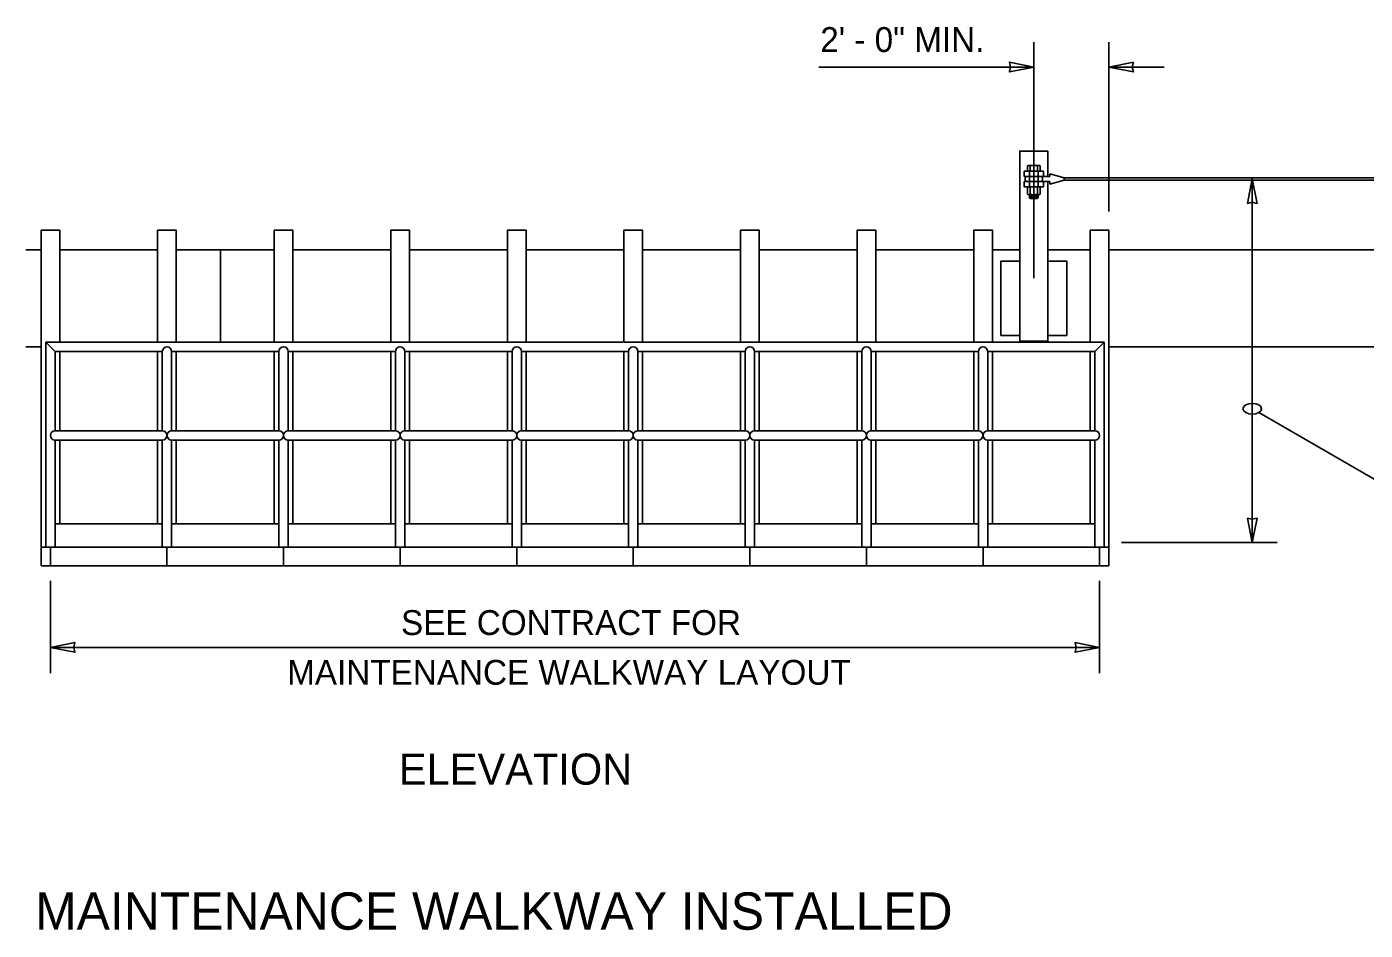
# Model space of a CAD drawing. Extents: x 99862 to 103151, y 100000 to 108076.
# Drawn here: x 100813 to 101674, y 101036 to 101617 of the extents above; entities that cross this region are included whole.
import ezdxf

# ---------------------------------------------------------------- set-up
doc = ezdxf.new("R2010")
doc.units = 0
for name, color, linetype in [('Level 15', 7, 'Continuous'), ('Level 18', 7, 'Continuous'), ('Level 2', 7, 'Continuous'), ('Level 20', 7, 'Continuous'), ('Level 22', 7, 'Continuous'), ('Level 23', 7, 'Continuous'), ('Level 27', 7, 'Continuous'), ('Level 4', 7, 'Continuous')]:
    doc.layers.add(name, color=color, linetype=linetype)

msp = doc.modelspace()

# ---------------------------------------------------------------- linework, layer by layer
at = {"layer": 'Level 15'}
for p, q in [((101460.79, 101607.01), (101460.79, 101455.11)), ((101509.12, 101498.01), (101509.12, 101607.01)), ((101322.46, 101591.01), (101460.79, 101591.01)), ((101509.12, 101591.01), (101544.63, 101591.01)), ((101601.38, 101519.01), (101601.38, 101285.01)), ((101605.62, 101368.72), (101682.77, 101324.18)), ((101517.12, 101285.01), (101617.38, 101285.01)), ((100828.12, 101260.38), (100828.12, 101201.02)), ((101503.12, 101260.38), (101503.12, 101201.02)), ((100828.12, 101217.57), (101503.12, 101217.57))]:
    msp.add_line(p, q, dxfattribs=at)
for points in [[(101460.79, 101591.01), (101445.07, 101587.93), (101445.8, 101591.01), (101445.07, 101594.09)], [(101509.12, 101591.01), (101524.85, 101594.09), (101524.12, 101591.01), (101524.85, 101587.93)], [(101601.38, 101519.01), (101604.46, 101503.28), (101601.38, 101504.01), (101598.29, 101503.28)], [(101601.38, 101285.01), (101604.46, 101300.73), (101601.38, 101300.01), (101598.29, 101300.73)], [(100828.12, 101217.57), (100843.85, 101214.48), (100843.12, 101217.57), (100843.85, 101220.65)], [(101503.12, 101217.57), (101487.4, 101220.65), (101488.12, 101217.57), (101487.4, 101214.48)]]:
    msp.add_lwpolyline(points, close=True, dxfattribs=at)
msp.add_ellipse((101601.38, 101371.17), major_axis=(-6, 0), ratio=0.57735, dxfattribs=at)
at = {"layer": 'Level 18'}
msp.add_line((101451.79, 101414.75), (101469.79, 101414.75), dxfattribs=at)
for points in [[(101451.79, 101537.01), (101451.79, 101537.01), (101469.79, 101537.01), (101469.79, 101520.65)], [(101451.79, 101414.75), (101451.79, 101537.01)], [(101469.79, 101517.33), (101469.79, 101414.75)]]:
    msp.add_lwpolyline(points, dxfattribs=at)
for points in [[(101451.79, 101466.2), (101439.61, 101466.2), (101439.61, 101418.32), (101451.79, 101418.32)], [(101469.79, 101466.2), (101481.98, 101466.2), (101481.98, 101418.32), (101469.79, 101418.32)]]:
    msp.add_lwpolyline(points, close=True, dxfattribs=at)
at = {"layer": 'Level 2'}
for p, q in [((100812.39, 101473.51), (100822.12, 101473.51)), ((100834.12, 101473.51), (100897.12, 101473.51)), ((100909.12, 101473.51), (100972.12, 101473.51)), ((100937.49, 101414.01), (100937.49, 101473.51)), ((100984.12, 101473.51), (101047.12, 101473.51)), ((101059.12, 101473.51), (101122.12, 101473.51)), ((101134.12, 101473.51), (101197.12, 101473.51)), ((101209.12, 101473.51), (101272.12, 101473.51)), ((101284.12, 101473.51), (101347.12, 101473.51)), ((101359.12, 101473.51), (101422.12, 101473.51)), ((101434.12, 101473.51), (101451.79, 101473.51)), ((101469.79, 101473.51), (101497.12, 101473.51)), ((101509.12, 101473.51), (101732.63, 101473.51)), ((100825.12, 101414.01), (100831.12, 101408.01)), ((101500.12, 101408.01), (101506.12, 101414.01)), ((100812.39, 101411.01), (100822.12, 101411.01)), ((101509.12, 101411.01), (102254.05, 101411.01))]:
    msp.add_line(p, q, dxfattribs=at)
for centre, start, end in [((100903.12, 101408.01), 0, 180), ((100978.12, 101408.01), 0, 180), ((101053.12, 101408.01), 0, 180), ((101128.12, 101408.01), 0, 180), ((101203.12, 101408.01), 0, 180), ((101278.12, 101408.01), 0, 180), ((101353.12, 101408.01), 0, 180), ((101428.12, 101408.01), 0, 180), ((100831.12, 101354.01), 90, 270), ((100900.12, 101354.01), 270, 90), ((100906.12, 101354.01), 90, 270), ((100975.12, 101354.01), 270, 90), ((100981.12, 101354.01), 90, 270), ((101050.12, 101354.01), 270, 90), ((101056.12, 101354.01), 90, 270), ((101125.12, 101354.01), 270, 90), ((101131.12, 101354.01), 90, 270), ((101200.12, 101354.01), 270, 90), ((101206.12, 101354.01), 90, 270), ((101275.12, 101354.01), 270, 90), ((101281.12, 101354.01), 90, 270), ((101350.12, 101354.01), 270, 90), ((101356.12, 101354.01), 90, 270), ((101425.12, 101354.01), 270, 90), ((101431.12, 101354.01), 90, 270), ((101500.12, 101354.01), 270, 90)]:
    msp.add_arc(centre, 3, start, end, dxfattribs=at)
at = {"layer": 'Level 22'}
for points in [[(100822.12, 101270.01), (100822.12, 101486.01), (100834.12, 101486.01), (100834.12, 101414.01)], [(100897.12, 101414.01), (100897.12, 101486.01), (100909.12, 101486.01), (100909.12, 101414.01)], [(100972.12, 101414.01), (100972.12, 101486.01), (100984.12, 101486.01), (100984.12, 101414.01)], [(101047.12, 101414.01), (101047.12, 101486.01), (101059.12, 101486.01), (101059.12, 101414.01)], [(101122.12, 101414.01), (101122.12, 101486.01), (101134.12, 101486.01), (101134.12, 101414.01)], [(101197.12, 101414.01), (101197.12, 101486.01), (101209.12, 101486.01), (101209.12, 101414.01)], [(101272.12, 101414.01), (101272.12, 101486.01), (101284.12, 101486.01), (101284.12, 101414.01)], [(101347.12, 101414.01), (101347.12, 101486.01), (101359.12, 101486.01), (101359.12, 101414.01)], [(101422.12, 101414.01), (101422.12, 101486.01), (101434.12, 101486.01), (101434.12, 101414.01)], [(101497.12, 101414.01), (101497.12, 101486.01), (101509.12, 101486.01), (101509.12, 101270.01)], [(100834.12, 101408.01), (100834.12, 101357.01)], [(100897.12, 101357.01), (100897.12, 101408.01)], [(100909.12, 101408.01), (100909.12, 101357.01)], [(100972.12, 101357.01), (100972.12, 101408.01)], [(100984.12, 101408.01), (100984.12, 101357.01)], [(101047.12, 101357.01), (101047.12, 101408.01)], [(101059.12, 101408.01), (101059.12, 101357.01)], [(101122.12, 101357.01), (101122.12, 101408.01)], [(101134.12, 101408.01), (101134.12, 101357.01)], [(101197.12, 101357.01), (101197.12, 101408.01)], [(101209.12, 101408.01), (101209.12, 101357.01)], [(101272.12, 101357.01), (101272.12, 101408.01)], [(101284.12, 101408.01), (101284.12, 101357.01)], [(101347.12, 101357.01), (101347.12, 101408.01)], [(101359.12, 101408.01), (101359.12, 101357.01)], [(101422.12, 101357.01), (101422.12, 101408.01)], [(101434.12, 101408.01), (101434.12, 101357.01)], [(101497.12, 101357.01), (101497.12, 101408.01)], [(100834.12, 101351.01), (100834.12, 101297.01)], [(100897.12, 101297.01), (100897.12, 101351.01)], [(100909.12, 101351.01), (100909.12, 101297.01)], [(100972.12, 101297.01), (100972.12, 101351.01)], [(100984.12, 101351.01), (100984.12, 101297.01)], [(101047.12, 101297.01), (101047.12, 101351.01)], [(101059.12, 101351.01), (101059.12, 101297.01)], [(101122.12, 101297.01), (101122.12, 101351.01)], [(101134.12, 101351.01), (101134.12, 101297.01)], [(101197.12, 101297.01), (101197.12, 101351.01)], [(101209.12, 101351.01), (101209.12, 101297.01)], [(101272.12, 101297.01), (101272.12, 101351.01)], [(101284.12, 101351.01), (101284.12, 101297.01)], [(101347.12, 101297.01), (101347.12, 101351.01)], [(101359.12, 101351.01), (101359.12, 101297.01)], [(101422.12, 101297.01), (101422.12, 101351.01)], [(101434.12, 101351.01), (101434.12, 101297.01)], [(101497.12, 101297.01), (101497.12, 101351.01)]]:
    msp.add_lwpolyline(points, dxfattribs=at)
at = {"layer": 'Level 23'}
for p, q in [((100834.12, 101282.01), (100822.12, 101282.01)), ((100828.12, 101270.01), (100828.12, 101282.01)), ((100909.12, 101282.01), (100897.12, 101282.01)), ((100903.12, 101270.01), (100903.12, 101282.01)), ((100984.12, 101282.01), (100972.12, 101282.01)), ((100978.12, 101270.01), (100978.12, 101282.01)), ((101059.12, 101282.01), (101047.12, 101282.01)), ((101053.12, 101270.01), (101053.12, 101282.01)), ((101134.12, 101282.01), (101122.12, 101282.01)), ((101128.12, 101270.01), (101128.12, 101282.01)), ((101209.12, 101282.01), (101197.12, 101282.01)), ((101203.12, 101270.01), (101203.12, 101282.01)), ((101284.12, 101282.01), (101272.12, 101282.01)), ((101278.12, 101270.01), (101278.12, 101282.01)), ((101359.12, 101282.01), (101347.12, 101282.01)), ((101353.12, 101270.01), (101353.12, 101282.01)), ((101434.12, 101282.01), (101422.12, 101282.01)), ((101428.12, 101270.01), (101428.12, 101282.01)), ((101509.12, 101282.01), (101497.12, 101282.01)), ((101503.12, 101270.01), (101503.12, 101282.01)), ((100834.12, 101270.01), (100822.12, 101270.01)), ((100909.12, 101270.01), (100897.12, 101270.01)), ((100984.12, 101270.01), (100972.12, 101270.01)), ((101059.12, 101270.01), (101047.12, 101270.01)), ((101134.12, 101270.01), (101122.12, 101270.01)), ((101209.12, 101270.01), (101197.12, 101270.01)), ((101284.12, 101270.01), (101272.12, 101270.01)), ((101359.12, 101270.01), (101347.12, 101270.01)), ((101434.12, 101270.01), (101422.12, 101270.01)), ((101509.12, 101270.01), (101497.12, 101270.01))]:
    msp.add_line(p, q, dxfattribs=at)
at = {"layer": 'Level 27'}
for p, q in [((100825.12, 101282.01), (100825.12, 101414.01)), ((100825.12, 101414.01), (101196.49, 101414.01)), ((101196.93, 101414.01), (101506.12, 101414.01)), ((101506.12, 101282.01), (101506.12, 101414.01)), ((100831.12, 101408.01), (100900.12, 101408.01)), ((100831.12, 101357.01), (100831.12, 101408.01)), ((100900.12, 101357.01), (100900.12, 101408.01)), ((100906.12, 101408.01), (100975.12, 101408.01)), ((100906.12, 101357.01), (100906.12, 101408.01)), ((100975.12, 101357.01), (100975.12, 101408.01)), ((100981.12, 101408.01), (101050.12, 101408.01)), ((100981.12, 101357.01), (100981.12, 101408.01)), ((101050.12, 101357.01), (101050.12, 101408.01)), ((101056.12, 101408.01), (101125.12, 101408.01)), ((101056.12, 101357.01), (101056.12, 101408.01)), ((101125.12, 101357.01), (101125.12, 101408.01)), ((101131.12, 101408.01), (101200.12, 101408.01)), ((101131.12, 101357.01), (101131.12, 101408.01)), ((101200.12, 101357.01), (101200.12, 101408.01)), ((101206.12, 101408.01), (101275.12, 101408.01)), ((101206.12, 101357.01), (101206.12, 101408.01)), ((101275.12, 101357.01), (101275.12, 101408.01)), ((101281.12, 101408.01), (101350.12, 101408.01)), ((101281.12, 101357.01), (101281.12, 101408.01)), ((101350.12, 101357.01), (101350.12, 101408.01)), ((101356.12, 101408.01), (101425.12, 101408.01)), ((101356.12, 101357.01), (101356.12, 101408.01)), ((101425.12, 101357.01), (101425.12, 101408.01)), ((101431.12, 101408.01), (101500.12, 101408.01)), ((101431.12, 101357.01), (101431.12, 101408.01)), ((101500.12, 101357.01), (101500.12, 101408.01)), ((100831.12, 101357.01), (100900.12, 101357.01)), ((100906.12, 101357.01), (100975.12, 101357.01)), ((100981.12, 101357.01), (101050.12, 101357.01)), ((101056.12, 101357.01), (101125.12, 101357.01)), ((101131.12, 101357.01), (101200.12, 101357.01)), ((101206.12, 101357.01), (101275.12, 101357.01)), ((101281.12, 101357.01), (101350.12, 101357.01)), ((101356.12, 101357.01), (101425.12, 101357.01)), ((101431.12, 101357.01), (101500.12, 101357.01)), ((100831.12, 101282.01), (100831.12, 101351.01)), ((100831.12, 101351.01), (100900.12, 101351.01)), ((100900.12, 101282.01), (100900.12, 101351.01)), ((100906.12, 101351.01), (100975.12, 101351.01)), ((100906.12, 101282.01), (100906.12, 101351.01)), ((100975.12, 101282.01), (100975.12, 101351.01)), ((100981.12, 101351.01), (101050.12, 101351.01)), ((100981.12, 101282.01), (100981.12, 101351.01)), ((101050.12, 101282.01), (101050.12, 101351.01)), ((101056.12, 101351.01), (101125.12, 101351.01)), ((101056.12, 101282.01), (101056.12, 101351.01)), ((101125.12, 101282.01), (101125.12, 101351.01)), ((101131.12, 101351.01), (101200.12, 101351.01)), ((101131.12, 101282.01), (101131.12, 101351.01)), ((101200.12, 101282.01), (101200.12, 101351.01)), ((101206.12, 101351.01), (101275.12, 101351.01)), ((101206.12, 101282.01), (101206.12, 101351.01)), ((101275.12, 101282.01), (101275.12, 101351.01)), ((101281.12, 101351.01), (101350.12, 101351.01)), ((101281.12, 101282.01), (101281.12, 101351.01)), ((101350.12, 101282.01), (101350.12, 101351.01)), ((101356.12, 101351.01), (101425.12, 101351.01)), ((101356.12, 101282.01), (101356.12, 101351.01)), ((101425.12, 101282.01), (101425.12, 101351.01)), ((101431.12, 101351.01), (101500.12, 101351.01)), ((101431.12, 101282.01), (101431.12, 101351.01)), ((101500.12, 101282.01), (101500.12, 101351.01)), ((100831.12, 101297.01), (100900.12, 101297.01)), ((100906.12, 101297.01), (100975.12, 101297.01)), ((100981.12, 101297.01), (101050.12, 101297.01)), ((101056.12, 101297.01), (101125.12, 101297.01)), ((101131.12, 101297.01), (101200.12, 101297.01)), ((101206.12, 101297.01), (101275.12, 101297.01)), ((101281.12, 101297.01), (101350.12, 101297.01)), ((101356.12, 101297.01), (101425.12, 101297.01)), ((101431.12, 101297.01), (101500.12, 101297.01)), ((100822.12, 101282.01), (101509.12, 101282.01)), ((100822.12, 101270.01), (101509.12, 101270.01))]:
    msp.add_line(p, q, dxfattribs=at)
at = {"layer": 'Level 4'}
for p, q in [((101456.68, 101524.02), (101456.68, 101527.4)), ((101457.54, 101527.67), (101464.03, 101527.67)), ((101458.42, 101527.4), (101458.42, 101524.02)), ((101463.17, 101527.4), (101463.17, 101524.02)), ((101464.9, 101524.02), (101464.9, 101527.4)), ((101454.53, 101524.02), (101467.06, 101524.02)), ((101454.53, 101520.65), (101454.53, 101524.02)), ((101454.53, 101520.65), (101471.08, 101520.65)), ((101454.53, 101517.33), (101471.08, 101517.33)), ((101454.53, 101513.95), (101454.53, 101517.33)), ((101458.05, 101513.95), (101458.05, 101524.02)), ((101463.53, 101513.95), (101463.53, 101524.02)), ((101467.06, 101520.65), (101467.06, 101524.02)), ((101467.06, 101513.95), (101467.06, 101517.33)), ((101471.08, 101520.65), (101471.08, 101522.33)), ((101471.08, 101522.33), (101480.41, 101519.84)), ((101471.08, 101515.69), (101480.41, 101518.18)), ((101471.08, 101515.69), (101471.08, 101517.33)), ((101480.41, 101519.84), (101480.41, 101518.18)), ((102119.77, 101519.82), (101480.41, 101519.82)), ((102119.77, 101518.16), (101480.41, 101518.16)), ((101454.53, 101513.95), (101467.06, 101513.95)), ((101456.68, 101513.95), (101464.9, 101513.95)), ((101456.68, 101509.16), (101456.68, 101513.95)), ((101457.54, 101508.88), (101464.03, 101508.88)), ((101458.05, 101506.92), (101458.05, 101508.88)), ((101458.05, 101507.91), (101463.53, 101507.91)), ((101458.42, 101513.95), (101458.42, 101509.16)), ((101458.88, 101508.41), (101462.7, 101508.41)), ((101458.88, 101507.42), (101462.7, 101507.42)), ((101463.17, 101513.95), (101463.17, 101509.16)), ((101463.53, 101506.92), (101463.53, 101508.88)), ((101464.9, 101509.16), (101464.9, 101513.95)), ((101458.05, 101506.92), (101463.53, 101506.92)), ((101458.05, 101506.92), (101458.34, 101506.42)), ((101458.34, 101506.42), (101463.24, 101506.42)), ((101463.53, 101506.92), (101463.24, 101506.42))]:
    msp.add_line(p, q, dxfattribs=at)
for centre, radius, start, end in [((101457.55, 101526.17), 1.5, 54.71987, 125.28013), ((101460.79, 101517.32), 10.35, 76.75036, 103.24964), ((101464.03, 101526.17), 1.5, 54.71987, 125.28013), ((101457.37, 101518.99), 2.22, 131.73582, 228.26418), ((101464.19, 101519.01), 2.22, 311.73582, 48.26418), ((101457.55, 101510.39), 1.5, 234.71987, 305.28013), ((101460.79, 101519.23), 10.35, 256.75036, 283.24964), ((101464.03, 101510.39), 1.5, 234.71987, 305.28013)]:
    msp.add_arc(centre, radius, start, end, dxfattribs=at)

# ---------------------------------------------------------------- texts
at = {"layer": 'Level 20'}
for s, height, p in [('2\' - 0" MIN.', 16, (101323.41, 101600.71)), ('SEE CONTRACT FOR', 16, (101053.68, 101225.57)), ('MAINTENANCE WALKWAY LAYOUT', 16, (100980.43, 101193.57)), (' ELEVATION', 20, (101044.88, 101129.28)), ('MAINTENANCE WALKWAY INSTALLED', 24, (100818.26, 101035.95))]:
    msp.add_text(s, height=height, dxfattribs=at).set_placement(p)

doc.saveas('drawing.dxf')
